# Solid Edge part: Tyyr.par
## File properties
Author: Olev
Template: Normal.par
Last saved by: Olev
Revision: 4
Application: Solid Edge
Accuracy: 0,990
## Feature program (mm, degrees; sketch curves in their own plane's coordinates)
sketch for "unnamed Protrusion 1" plane through (0, 0, 0) normal (1, 0, 0) x-axis (0, 1, 0)
  line (0, 0) -> (0, 0)
  line (0, 0) -> (0, 0)
  line (0, 0) -> (0, 17)
  line (0, 17) -> (14, 17)
  line (14, 17) -> (14, 0)
  line (14, 0) -> (0, 0)
extrude "unnamed Protrusion 1" add finite 6 symmetric
sketch for "ExtrudedCutout_1" #1 plane through (0, 7, 17) normal (0, 0, 1) x-axis (1, 0, 0)
  bspline degree 3 poles (0, 7) (-0.1429, 7.0211) (-0.6548, 6.4124) (-1.759, 2.6015) (-1.8838, -4.2534) (-0.9006, -6.5739) (-0.3895, -6.9579) (0, -7) knots 0 0.0975 0.3201 0.8014 0.8702 1 multiplicities 4 1 1 1 1 4
  bspline degree 3 poles (0, 7) (0.1429, 7.0211) (0.6548, 6.4124) (1.759, 2.6015) (1.8838, -4.2534) (0.9006, -6.5739) (0.3895, -6.9579) (0, -7) knots 0 0.0975 0.3201 0.8014 0.8702 1 multiplicities 4 1 1 1 1 4
sketch for "ExtrudedCutout_1" #2 plane through (0, 7, 17) normal (0, 0, 1) x-axis (1, 0, 0)
  line (0, 7.7787) -> (-4.0032, 7.7787)
  line (-4.0032, 7.7787) -> (-4.0032, -7.539)
  line (-4.0032, -7.539) -> (0, -7.539)
  line (4.0032, -7.539) -> (0, -7.539)
  line (4.0032, 7.7787) -> (4.0032, -7.539)
  line (0, 7.7787) -> (4.0032, 7.7787)
extrude "ExtrudedCutout_1" cut finite 27.052 along -normal
sketch for "ExtrudedProtrusion_2" plane through (0, 7, 17) normal (0, 0, 1) x-axis (1, 0, 0)
  circle centre (0, -5.4295) radius 0.7983
extrude "ExtrudedProtrusion_2" add finite 3.7311 along +normal
chamfer "Chamfer_1" setback 0.2
sketch for "unnamed RevolvedProtrusion 1" plane through (0, 0, 0) normal (1, 0, 0) x-axis (0, 1, 0)
  line (0.7722, 17.9103) -> (0.4507, 17.9103)
  line (0.4507, 17.9103) -> (0.4507, 17)
  line (0.4507, 17) -> (0.7722, 17)
  line (0.7722, 17) -> (0.7722, 17.9103)
revolve "unnamed RevolvedProtrusion 1" add full turn 360 deg about sketch line (1.5705, 20.7311) -> (1.5705, 16.7169)
fillet "Round_3" radius 0.1
fillet "Round_4" radius 0.1
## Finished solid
Body 1: solid body, 21 faces, 39 edges, 20 vertices.
  Faces by surface: blend 6, plane 6, cylinder 4, swept 2, torus 2, cone 1
  Edges by curve: intersection 20, circle 12, line 7
Bounding box of the edges (mm; curved faces can reach further): 3.396 x 14.000 x 20.731, from (-1.6979, 0, 0) to (1.6979, 14, 20.7311).
Cylindrical faces by radius (mm): R0.1 x2, R0.7983 x1, R1.1198 x1
Conical faces (half-angle, radius in mm at the cone's reference point): 45 deg R0.7983 x1
Toroidal faces (ring radius, tube radius in mm): R1.2198 r0.1 x2
Planar faces by outward normal: +y 1, +z 4, -z 1
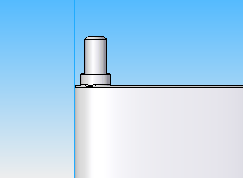
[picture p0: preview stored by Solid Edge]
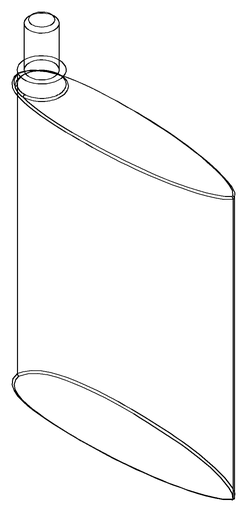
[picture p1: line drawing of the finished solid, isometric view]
